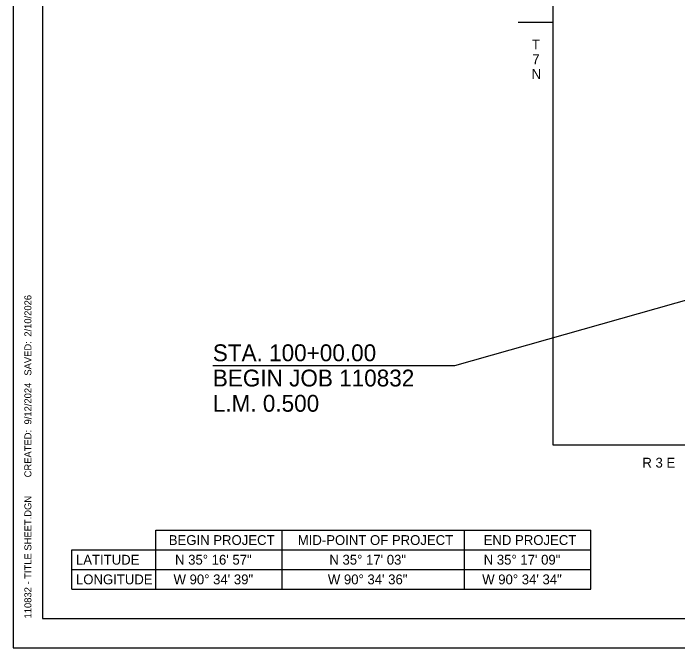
# Model space of a CAD drawing. Extents: x -0.68 to 1.92, y 0 to 0.95.
# Drawn here: x 0 to 0.4736, y 0 to 0.4519 of the extents above; entities that cross this region are included whole.
import ezdxf

# ---------------------------------------------------------------- set-up
doc = ezdxf.new("R2010")
doc.units = 0
for name, color, linetype in [('Default', 7, 'Continuous'), ('DSN_DRFT_DNC', 7, 'Continuous'), ('DSN_DRFT_Guideline-No-Plot', 7, 'Continuous'), ('SHET_Annotations', 7, 'Continuous'), ('SHET_Border-Lines', 7, 'Continuous'), ('SHET_Border-Text', 7, 'Continuous')]:
    doc.layers.add(name, color=color, linetype=linetype)

msp = doc.modelspace()

# ---------------------------------------------------------------- linework, layer by layer
at = {"layer": 'Default'}
for p, q in [((0.31471, 0.20092), (0.54446, 0.26626)), ((0.14221, 0.20092), (0.31471, 0.20092))]:
    msp.add_line(p, q, dxfattribs=at)
at = {"layer": 'DSN_DRFT_DNC'}
msp.add_lwpolyline([(0.38477, 0.54167), (1.0319, 0.54167), (1.0319, 0.1443), (0.38477, 0.1443)], close=True, dxfattribs=at)
at = {"layer": 'DSN_DRFT_Guideline-No-Plot'}
msp.add_lwpolyline([(0, 0), (1.41667, 0), (1.41667, 0.91667), (0, 0.91667)], close=True, dxfattribs=at)
at = {"layer": 'SHET_Annotations'}
msp.add_line((0.35977, 0.44566), (0.38477, 0.44566), dxfattribs=at)
at = {"layer": 'SHET_Border-Lines'}
msp.add_lwpolyline([(0.02083, 0.02083), (1.39583, 0.02083), (1.39583, 0.89583), (0.02083, 0.89583)], close=True, dxfattribs=at)
at = {"layer": 'SHET_Border-Text'}
for p, q in [((0.10167, 0.04167), (0.10167, 0.08367)), ((0.10167, 0.08367), (0.41167, 0.08367)), ((0.19167, 0.04167), (0.19167, 0.08367)), ((0.32167, 0.04167), (0.32167, 0.08367)), ((0.41167, 0.04167), (0.41167, 0.08367)), ((0.04167, 0.04167), (0.04167, 0.06967)), ((0.04167, 0.06967), (0.41167, 0.06967)), ((0.04167, 0.05567), (0.41167, 0.05567)), ((0.04167, 0.04167), (0.41167, 0.04167))]:
    msp.add_line(p, q, dxfattribs=at)

# ---------------------------------------------------------------- texts
at = {"layer": 'Default'}
for s, p in [('STA. 100+00.00', (0.14221, 0.20409)), ('BEGIN JOB 110832', (0.14221, 0.18609)), ('L.M. 0.500', (0.14221, 0.16809))]:
    msp.add_text(s, height=0.012, dxfattribs=at).set_placement(p)
at = {"layer": 'SHET_Annotations'}
for s, p in [('T', (0.36963, 0.42616)), ('7', (0.3699, 0.41566)), ('N', (0.36947, 0.40516)), ('R 3 E', (0.4484, 0.1283)), ('N 35° 16\' 57"', (0.11529, 0.05917)), ('N 35° 17\' 03"', (0.22529, 0.05917)), ('N 35° 17\' 09"', (0.33529, 0.05917)), ('W 90° 34\' 39"', (0.11423, 0.04517)), ('W 90° 34\' 36"', (0.22423, 0.04517)), ('W 90° 34\' 34"', (0.33423, 0.04517))]:
    msp.add_text(s, height=0.007, dxfattribs=at).set_placement(p)
at = {"layer": 'SHET_Border-Text'}
for s, p in [('2/10/2026', (0.01292, 0.22154)), ('2/10/2026', (0.01292, 0.22154)), ('  SAVED: ', (0.01292, 0.19009)), ('  SAVED: ', (0.01292, 0.19009)), ('9/12/2024', (0.01292, 0.15903)), ('9/12/2024', (0.01292, 0.15903)), ('     CREATED: ', (0.01292, 0.11206)), ('     CREATED: ', (0.01292, 0.11206)), ('110832 - TITLE SHEET.DGN', (0.01292, 0.02083)), ('110832 - TITLE SHEET.DGN', (0.01292, 0.02083))]:
    msp.add_text(s, height=0.005, rotation=90, dxfattribs=at).set_placement(p)
for s, p in [('BEGIN PROJECT', (0.11082, 0.07317)), ('MID-POINT OF PROJECT', (0.20277, 0.07317)), ('END PROJECT', (0.33526, 0.07317)), ('LATITUDE', (0.04467, 0.05917)), ('LONGITUDE', (0.04467, 0.04517))]:
    msp.add_text(s, height=0.007, dxfattribs=at).set_placement(p)

doc.saveas('drawing.dxf')
